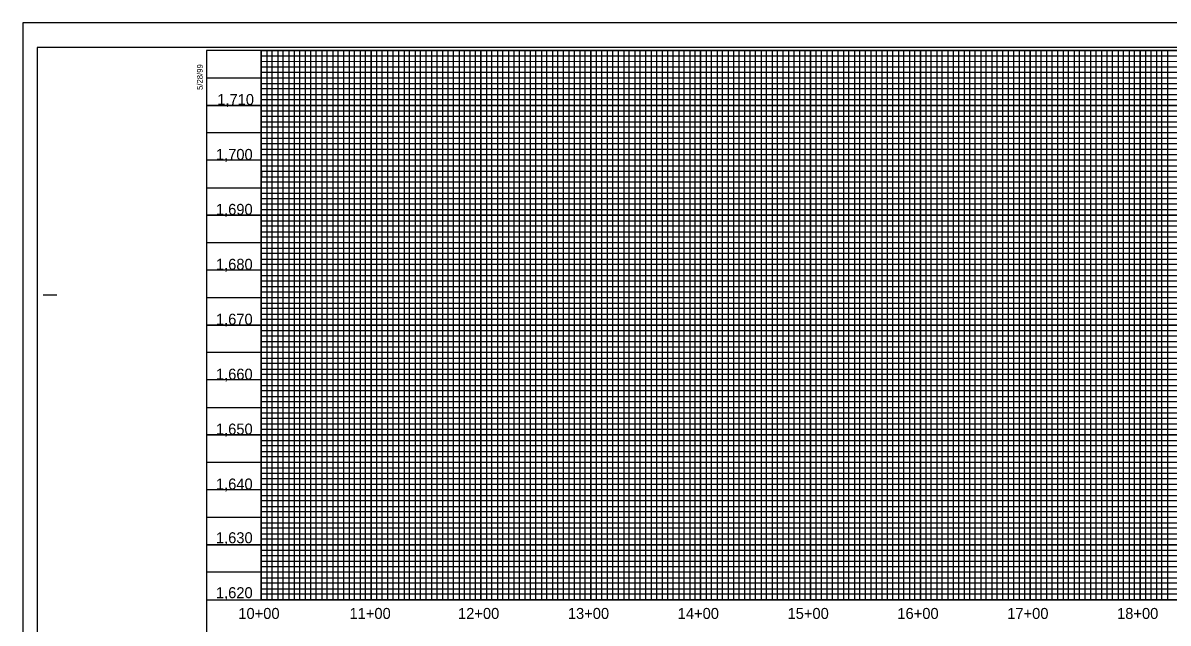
# Model space of a CAD drawing. Extents: x 497599 to 513368, y 404140 to 476034.
# Drawn here: x 505692 to 506734, y 439315 to 439861 of the extents above; entities that cross this region are included whole.
import ezdxf

# ---------------------------------------------------------------- set-up
doc = ezdxf.new("R2010")
doc.units = 0
for name, color, linetype in [('Exist Vertical Profile Vertical Axis Label', 7, 'Continuous'), ('Sheet Cutting Line CELL', 7, 'Continuous'), ('Sheet DOT Grid CELL', 7, 'Continuous'), ('Sheet Layout Profile Border Port 2', 7, 'Continuous'), ('Sheet Plot Border Inside CELL', 7, 'Continuous'), ('Sheet Plot Border Outside CELL', 7, 'Continuous'), ('Sheet Profile CELL', 7, 'Continuous'), ('Sheet Profile Grid Major CELL', 7, 'Continuous'), ('Sheet Profile Grid Middle CELL', 7, 'Continuous'), ('Sheet Profile Grid Minor CELL', 7, 'Continuous')]:
    doc.layers.add(name, color=color, linetype=linetype)

msp = doc.modelspace()

# ---------------------------------------------------------------- linework, layer by layer
at = {"layer": 'Sheet Cutting Line CELL'}
for p, q in [((507375.7, 439861.1), (505691.7, 439861.1)), ((505691.7, 439861.1), (505691.7, 438761.1))]:
    msp.add_line(p, q, dxfattribs=at)
at = {"layer": 'Sheet DOT Grid CELL'}
for p, q in [((505908.7, 439336.1), (505908.7, 439836.1)), ((505958.7, 439336.1), (505958.7, 439836.1)), ((506008.7, 439336.1), (506008.7, 439836.1)), ((506058.7, 439336.1), (506058.7, 439836.1)), ((506108.7, 439336.1), (506108.7, 439836.1)), ((506158.7, 439336.1), (506158.7, 439836.1)), ((506208.7, 439336.1), (506208.7, 439836.1)), ((506258.7, 439336.1), (506258.7, 439836.1)), ((506308.7, 439336.1), (506308.7, 439836.1)), ((506358.7, 439336.1), (506358.7, 439836.1)), ((506408.7, 439336.1), (506408.7, 439836.1)), ((506458.7, 439336.1), (506458.7, 439836.1)), ((506508.7, 439336.1), (506508.7, 439836.1)), ((506558.7, 439336.1), (506558.7, 439836.1)), ((506608.7, 439336.1), (506608.7, 439836.1)), ((506658.7, 439336.1), (506658.7, 439836.1)), ((506708.7, 439336.1), (506708.7, 439836.1)), ((507158.6, 439786.1), (505858.7, 439786.1)), ((507158.6, 439736.1), (505858.7, 439736.1)), ((507158.7, 439686.1), (505858.7, 439686.1)), ((507358.7, 439636.1), (505858.7, 439636.1)), ((507358.7, 439586.1), (505858.7, 439586.1)), ((507358.7, 439536.1), (505858.7, 439536.1)), ((507358.7, 439486.1), (505858.7, 439486.1)), ((507358.7, 439436.1), (505858.7, 439436.1)), ((507358.7, 439386.1), (505858.7, 439386.1))]:
    msp.add_line(p, q, dxfattribs=at)
at = {"layer": 'Sheet Layout Profile Border Port 2'}
msp.add_lwpolyline([(505908.7, 439836.1), (507308.7, 439836.1), (507308.7, 439336.1), (505908.7, 439336.1)], close=True, dxfattribs=at)
at = {"layer": 'Sheet Plot Border Inside CELL'}
msp.add_lwpolyline([(505704.7, 438783.6), (507371.2, 438783.6), (507371.2, 439838.7), (505704.7, 439838.7)], close=True, dxfattribs=at)
at = {"layer": 'Sheet Plot Border Outside CELL'}
msp.add_lwpolyline([(505691.7, 438761.1), (507375.7, 438761.1), (507375.7, 439861.1), (505691.7, 439861.1)], close=True, dxfattribs=at)
at = {"layer": 'Sheet Profile CELL'}
for p, q in [((505710.2, 439613.6), (505722.7, 439613.6)), ((505858.7, 439336.1), (507358.7, 439336.1))]:
    msp.add_line(p, q, dxfattribs=at)
msp.add_lwpolyline([(507358.7, 439836.1), (505858.7, 439836.1), (505858.7, 438786.1), (507358.7, 438786.1)], close=True, dxfattribs=at)
at = {"layer": 'Sheet Profile Grid Major CELL'}
for points in [[(505908.7, 439836.1), (505908.7, 439336.1), (505958.7, 439336.1), (505958.7, 439836.1), (506008.7, 439836.1), (506008.7, 439336.1), (506058.7, 439336.1), (506058.7, 439836.1), (506108.7, 439836.1), (506108.7, 439336.1), (506158.7, 439336.1), (506158.7, 439836.1), (506208.7, 439836.1), (506208.7, 439336.1), (506258.7, 439336.1), (506258.7, 439836.1), (506308.7, 439836.1), (506308.7, 439336.1), (506358.7, 439336.1), (506358.7, 439836.1), (506408.7, 439836.1), (506408.7, 439336.1), (506458.7, 439336.1), (506458.7, 439836.1), (506508.7, 439836.1), (506508.7, 439336.1), (506558.7, 439336.1), (506558.7, 439836.1), (506608.7, 439836.1), (506608.7, 439336.1), (506658.7, 439336.1), (506658.7, 439836.1), (506708.7, 439836.1), (506708.7, 439336.1), (506758.7, 439336.1)], [(505858.7, 439786.1), (507158.7, 439786.1)], [(507158.7, 439736.1), (505858.7, 439736.1), (505858.7, 439686.1), (507158.7, 439686.1)], [(507358.7, 439636.1), (505858.7, 439636.1), (505858.7, 439586.1), (507358.7, 439586.1)], [(507358.7, 439536.1), (505858.7, 439536.1), (505858.7, 439486.1), (507358.7, 439486.1)], [(507358.7, 439436.1), (505858.7, 439436.1), (505858.7, 439436.1), (505858.7, 439386.1), (507358.7, 439386.1)]]:
    msp.add_lwpolyline(points, dxfattribs=at)
at = {"layer": 'Sheet Profile Grid Middle CELL'}
msp.add_line((505858.7, 439811.1), (507158.6, 439811.1), dxfattribs=at)
for points in [[(505933.7, 439836.1), (505933.7, 439336.1), (505983.7, 439336.1), (505983.7, 439836.1), (506033.7, 439836.1), (506033.7, 439336.1), (506083.7, 439336.1), (506083.7, 439836.1), (506133.7, 439836.1), (506133.7, 439336.1), (506183.7, 439336.1), (506183.7, 439836.1), (506233.7, 439836.1), (506233.7, 439336.1), (506283.7, 439336.1), (506283.7, 439836.1), (506333.7, 439836.1), (506333.7, 439336.1), (506383.7, 439336.1), (506383.7, 439836.1), (506433.7, 439836.1), (506433.7, 439336.1), (506483.7, 439336.1), (506483.7, 439336.1), (506483.7, 439836.1), (506533.7, 439836.1), (506533.7, 439336.1), (506583.7, 439336.1), (506583.7, 439836.1), (506633.7, 439836.1), (506633.7, 439336.1), (506683.7, 439336.1), (506683.7, 439836.1), (506733.7, 439836.1), (506733.7, 439336.1), (506783.7, 439336.1)], [(507158.7, 439761.1), (505858.7, 439761.1), (505858.7, 439711.1), (507158.7, 439711.1)], [(507358.7, 439661.1), (505858.7, 439661.1), (505858.7, 439611.1), (507183.7, 439611.1)], [(507358.7, 439561.1), (505858.7, 439561.1), (505858.7, 439511.1), (507358.7, 439511.1)], [(507358.7, 439461.1), (505858.7, 439461.1), (505858.7, 439411.1), (507358.7, 439411.1)], [(507358.7, 439361.1), (505858.7, 439361.1)]]:
    msp.add_lwpolyline(points, dxfattribs=at)
at = {"layer": 'Sheet Profile Grid Minor CELL'}
for p, q in [((505908.7, 439831.1), (507158.7, 439831.1)), ((505908.7, 439826.1), (505908.7, 439826.1)), ((507158.7, 439826.1), (505908.7, 439825.8)), ((505908.7, 439821.1), (507158.7, 439821.1)), ((507158.6, 439701.1), (505908.7, 439701.1)), ((507158.7, 439696.1), (505908.7, 439696.1)), ((507158.7, 439691.1), (505908.7, 439691.1)), ((505908.7, 439681.1), (507158.7, 439681.1)), ((507158.7, 439676.1), (505908.7, 439676.1)), ((505908.7, 439671.1), (507308.7, 439671.1)), ((507308.7, 439651.1), (505908.7, 439651.1)), ((505908.7, 439646.1), (507308.7, 439646.1)), ((507308.7, 439626.1), (505908.7, 439626.1)), ((505908.7, 439621.1), (507308.7, 439621.1)), ((507308.7, 439601.1), (505908.7, 439601.1)), ((505908.7, 439596.1), (507308.7, 439596.1)), ((507308.7, 439591.1), (505908.7, 439591.1)), ((505908.7, 439581.1), (507308.7, 439581.1)), ((507308.7, 439576.1), (505908.7, 439576.1)), ((505908.7, 439571.1), (507308.7, 439571.1)), ((507308.7, 439566.1), (505908.7, 439566.1)), ((505908.7, 439556.1), (507308.7, 439556.1)), ((507308.7, 439551.1), (505908.7, 439551.1)), ((505908.7, 439546.1), (507308.7, 439546.1)), ((507308.7, 439541.1), (505908.7, 439541.1)), ((505908.7, 439531.1), (507308.7, 439531.1)), ((507308.7, 439526.1), (505908.7, 439526.1)), ((505908.7, 439521.1), (507308.7, 439521.1)), ((507308.7, 439516.1), (505908.7, 439516.1)), ((505908.7, 439506.1), (507308.7, 439506.1)), ((507308.7, 439501.1), (505908.7, 439501.1)), ((505908.7, 439496.1), (507308.7, 439496.1)), ((507308.7, 439491.1), (505908.7, 439491.1)), ((505908.7, 439481.1), (507308.7, 439481.1)), ((507308.7, 439476.1), (505908.7, 439476.1)), ((505908.7, 439471.1), (507308.7, 439471.1)), ((507308.7, 439466.1), (505908.7, 439466.1)), ((505908.7, 439456.1), (507308.7, 439456.1)), ((507308.7, 439451.1), (505908.7, 439451.1)), ((507308.7, 439446.1), (505908.7, 439446.1)), ((507308.7, 439441.1), (505908.7, 439441.1)), ((505908.7, 439431.1), (507308.7, 439431.1)), ((507308.7, 439426.1), (505908.7, 439426.1)), ((505908.7, 439421.1), (507308.7, 439421.1)), ((507308.7, 439416.1), (505908.7, 439416.1)), ((505908.7, 439406.1), (507308.7, 439406.1)), ((507308.7, 439401.1), (505908.7, 439401.1)), ((505908.7, 439396.1), (507308.7, 439396.1)), ((507308.7, 439391.1), (505908.7, 439391.1)), ((505908.7, 439381.1), (507308.7, 439381.1)), ((507308.7, 439376.1), (505908.7, 439376.1)), ((505908.7, 439371.1), (507308.7, 439371.1)), ((507308.7, 439366.1), (505908.7, 439366.1)), ((505908.7, 439356.1), (507308.7, 439356.1)), ((507308.7, 439351.1), (505908.7, 439351.1)), ((505908.7, 439346.1), (507308.7, 439346.1))]:
    msp.add_line(p, q, dxfattribs=at)
for points in [[(505913.7, 439836.1), (505913.7, 439336.1), (505918.7, 439336.1), (505918.7, 439836.1), (505923.7, 439836.1), (505923.7, 439336.1), (505928.7, 439336.1), (505928.7, 439836.1), (505938.7, 439836.1), (505938.7, 439336.1), (505943.7, 439336.1), (505943.7, 439836.1), (505948.7, 439836.1), (505948.7, 439336.1), (505953.7, 439336.1), (505963.7, 439336.1), (505968.7, 439336.1), (505968.7, 439836.1), (505973.7, 439836.1), (505973.7, 439336.1), (505978.7, 439336.1), (505978.7, 439836.1), (505988.7, 439836.1), (505988.7, 439336.1), (505993.7, 439336.1), (505993.7, 439836.1), (505998.7, 439836.1), (505998.7, 439336.1), (506003.7, 439336.1), (506003.7, 439836.1), (506013.7, 439836.1), (506013.7, 439336.1), (506018.7, 439336.1), (506018.7, 439836.1), (506023.7, 439836.1), (506023.7, 439336.1), (506028.7, 439336.1), (506028.7, 439836.1), (506038.7, 439836.1), (506038.7, 439336.1), (506043.7, 439336.1), (506043.7, 439836.1), (506048.7, 439836.1), (506048.7, 439336.1), (506053.7, 439336.1), (506053.7, 439836.1), (506063.7, 439836.1), (506063.7, 439336.1), (506068.7, 439336.1), (506068.7, 439836.1), (506073.7, 439836.1), (506073.7, 439336.1), (506078.7, 439336.1), (506078.7, 439836.1), (506088.7, 439836.1), (506088.7, 439336.1), (506093.7, 439336.1), (506093.7, 439836.1), (506098.7, 439836.1), (506098.7, 439336.1), (506103.7, 439336.1), (506103.7, 439836.1), (506113.7, 439836.1), (506113.7, 439336.1), (506118.7, 439336.1), (506118.7, 439836.1), (506123.7, 439836.1), (506123.7, 439336.1)], [(505953.7, 439336.1), (505953.7, 439836.1), (505963.7, 439836.1), (505963.7, 439336.1)], [(506123.7, 439336.1), (506128.7, 439336.1), (506128.7, 439836.1), (506138.7, 439836.1), (506138.7, 439336.1), (506143.7, 439336.1), (506143.7, 439836.1), (506148.7, 439836.1), (506148.7, 439336.1), (506153.7, 439336.1), (506153.7, 439836.1), (506163.7, 439836.1), (506163.7, 439336.1), (506168.7, 439336.1), (506168.7, 439836.1), (506173.7, 439836.1), (506173.7, 439336.1), (506178.7, 439336.1), (506178.7, 439836.1), (506188.7, 439836.1), (506188.7, 439336.1), (506193.7, 439336.1), (506193.7, 439836.1), (506198.7, 439836.1), (506198.7, 439336.1), (506203.7, 439336.1), (506203.7, 439836.1), (506213.7, 439836.1), (506213.7, 439336.1), (506218.7, 439336.1), (506218.7, 439836.1), (506223.7, 439836.1), (506223.7, 439336.1), (506228.7, 439336.1), (506228.7, 439836.1), (506238.7, 439836.1), (506238.7, 439336.1), (506243.7, 439336.1), (506243.7, 439836.1), (506248.7, 439836.1), (506248.7, 439336.1), (506253.7, 439336.1), (506253.7, 439836.1), (506263.7, 439836.1), (506263.7, 439336.1), (506268.7, 439336.1), (506268.7, 439836.1), (506273.7, 439836.1), (506273.7, 439336.1), (506278.7, 439336.1), (506278.7, 439836.1), (506288.7, 439836.1), (506288.7, 439336.1), (506293.7, 439336.1), (506293.7, 439836.1), (506298.7, 439836.1), (506298.7, 439336.1), (506303.7, 439336.1), (506303.7, 439836.1), (506313.7, 439836.1), (506313.7, 439336.1), (506318.7, 439336.1), (506318.7, 439836.1), (506323.7, 439836.1), (506323.7, 439336.1), (506328.7, 439336.1), (506328.7, 439836.1), (506338.7, 439836.1), (506338.7, 439336.1), (506343.7, 439336.1), (506343.7, 439836.1), (506348.7, 439836.1), (506348.7, 439336.1), (506353.7, 439336.1), (506353.7, 439836.1), (506363.7, 439836.1), (506363.7, 439336.1), (506368.7, 439336.1), (506368.7, 439836.1), (506373.7, 439836.1), (506373.7, 439336.1), (506378.7, 439336.1), (506378.7, 439836.1), (506388.7, 439836.1), (506388.7, 439336.1), (506393.7, 439336.1), (506393.7, 439836.1), (506398.7, 439836.1), (506398.7, 439336.1), (506403.7, 439336.1), (506403.7, 439836.1), (506413.7, 439836.1), (506413.7, 439336.1), (506418.7, 439336.1), (506418.7, 439836.1), (506423.7, 439836.1), (506423.7, 439336.1), (506428.7, 439336.1), (506428.7, 439836.1), (506438.7, 439836.1)], [(506438.7, 439836.1), (506438.7, 439336.1), (506443.7, 439336.1), (506443.7, 439836.1), (506448.7, 439836.1), (506448.7, 439336.1), (506453.7, 439336.1), (506453.7, 439836.1), (506463.7, 439836.1), (506463.7, 439336.1), (506468.7, 439336.1), (506468.7, 439836.1), (506473.7, 439836.1), (506473.7, 439336.1), (506478.7, 439336.1), (506478.7, 439836.1), (506488.7, 439836.1), (506488.7, 439336.1), (506493.7, 439336.1), (506493.7, 439836.1), (506498.7, 439836.1), (506498.7, 439336.1), (506503.7, 439336.1), (506503.7, 439836.1), (506513.7, 439836.1), (506513.7, 439336.1), (506518.7, 439336.1), (506518.7, 439836.1), (506523.7, 439836.1), (506523.7, 439336.1), (506528.7, 439336.1), (506528.7, 439836.1), (506538.7, 439836.1), (506538.7, 439336.1), (506543.7, 439336.1), (506543.7, 439836.1), (506548.7, 439836.1), (506548.7, 439336.1), (506553.7, 439336.1), (506553.7, 439836.1), (506563.7, 439836.1), (506563.7, 439336.1), (506563.7, 439336.1), (506568.7, 439336.1), (506568.7, 439836.1), (506573.7, 439836.1), (506573.7, 439336.1), (506578.7, 439336.1), (506578.7, 439836.1), (506588.7, 439836.1), (506588.7, 439336.1), (506593.7, 439336.1), (506593.7, 439836.1), (506598.7, 439836.1), (506598.7, 439336.1), (506603.7, 439336.1), (506603.7, 439836.1), (506613.7, 439836.1), (506613.7, 439336.1), (506618.7, 439336.1), (506618.7, 439836.1), (506623.7, 439836.1), (506623.7, 439336.1), (506628.7, 439336.1), (506628.7, 439836.1), (506638.7, 439836.1), (506638.7, 439336.1), (506643.7, 439336.1), (506643.7, 439836.1), (506648.7, 439836.1), (506648.7, 439336.1), (506653.7, 439336.1), (506653.7, 439836.1), (506663.7, 439836.1), (506663.7, 439336.1), (506668.7, 439336.1), (506668.7, 439836.1), (506673.7, 439836.1), (506673.7, 439336.1), (506678.7, 439336.1), (506678.7, 439836.1), (506688.7, 439836.1), (506688.7, 439336.1), (506693.7, 439336.1), (506693.7, 439836.1), (506698.7, 439836.1), (506698.7, 439336.1), (506703.7, 439336.1), (506703.7, 439836.1), (506713.7, 439836.1), (506713.7, 439336.1), (506718.4, 439336.7), (506718.7, 439336.1), (506718.7, 439836.1), (506723.7, 439836.1), (506723.7, 439336.1), (506728.7, 439336.1), (506728.7, 439836.1), (506738.7, 439836.1)], [(507158.7, 439816.1), (505908.7, 439816.1), (505908.7, 439806.1), (507158.7, 439806.1)], [(507158.6, 439801.1), (505908.7, 439801.1), (505908.7, 439796.1), (507158.7, 439796.1)], [(507158.7, 439791.1), (505908.7, 439791.1), (505908.7, 439781.1), (507158.7, 439781.1)], [(507158.7, 439776.1), (505908.7, 439776.1), (505908.7, 439771.1), (507158.7, 439771.1)], [(507158.7, 439766.1), (505908.7, 439766.1), (505908.7, 439756.1), (507158.7, 439756.1)], [(507158.7, 439751.1), (505908.7, 439751.1), (505908.7, 439746.1), (507158.7, 439746.1)], [(507158.7, 439741.1), (505908.7, 439741.1), (505908.7, 439731.1), (507158.7, 439731.1)], [(507158.7, 439726), (505908.8, 439726), (505908.8, 439721.1), (507158.7, 439721.1)], [(507158.7, 439716.1), (505908.7, 439716.1), (505908.7, 439706.1), (507158.7, 439706.1)], [(507308.7, 439666.1), (505908.7, 439666.1), (505908.7, 439656.1), (507308.7, 439656.1)], [(507308.7, 439641.1), (505908.7, 439641.1), (505908.7, 439631.1), (507308.7, 439631.1)], [(507308.7, 439616.1), (505908.7, 439616.1), (505908.7, 439606.1), (507308.7, 439606.1)], [(507308.7, 439341.1), (505908.7, 439341.1)]]:
    msp.add_lwpolyline(points, dxfattribs=at)

# ---------------------------------------------------------------- texts
at = {"layer": 'Exist Vertical Profile Vertical Axis Label'}
for s, p in [('1,710', (505868.6, 439786.4)), ('1,700', (505867.4, 439736.4)), ('1,690', (505867.4, 439686.4)), ('1,680', (505867.4, 439636.4)), ('1,670', (505867.4, 439586.4)), ('1,660', (505867.4, 439536.4)), ('1,650', (505867.4, 439486.4)), ('1,640', (505867.4, 439436.4)), ('1,630', (505867.4, 439387.5)), ('1,620', (505867.4, 439337.5)), ('10+00', (505887.8, 439318.6)), ('11+00', (505989, 439318.6)), ('12+00', (506087.8, 439318.6)), ('13+00', (506187.8, 439318.6)), ('14+00', (506287.8, 439318.6)), ('15+00', (506387.8, 439318.6)), ('16+00', (506487.8, 439318.6)), ('17+00', (506587.8, 439318.6)), ('18+00', (506687.8, 439318.6))]:
    msp.add_text(s, height=10, dxfattribs=at).set_placement(p)
at = {"layer": 'Sheet Profile CELL'}
msp.add_text('5/28/99', height=5.25, rotation=90, dxfattribs=at).set_placement((505855.4, 439800.1))

doc.saveas('drawing.dxf')
